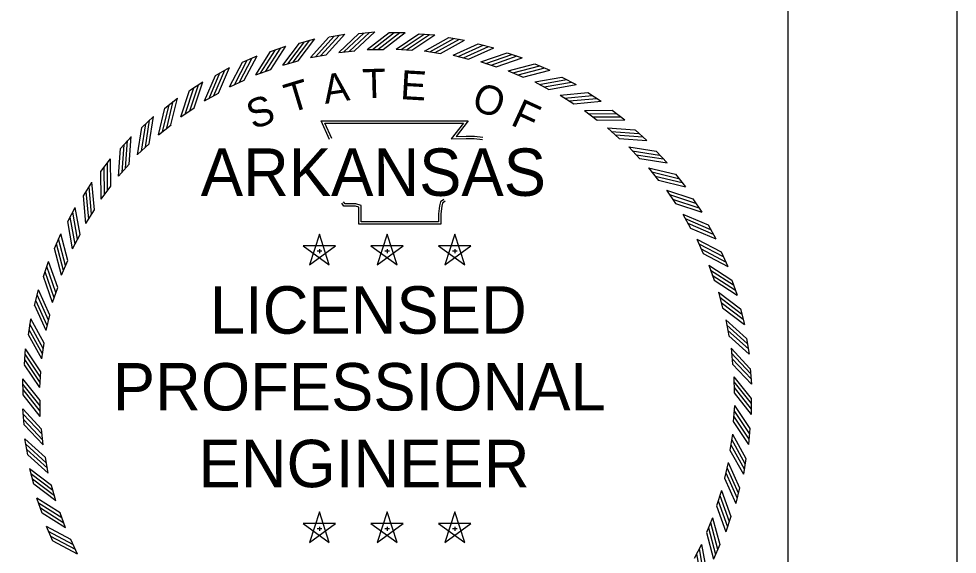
# Model space of a CAD drawing. Extents: x 0 to 1228740, y 0 to 152440.
# Drawn here: x 30.801 to 34, y 18.239 to 20.064 of the extents above; entities that cross this region are included whole.
import ezdxf

# ---------------------------------------------------------------- set-up
doc = ezdxf.new("R2010")
doc.units = 0
doc.layers.add('R_Border', color=7, linetype='Continuous')
doc.layers.add('STAMP', color=7, linetype='Continuous')

msp = doc.modelspace()

# ---------------------------------------------------------------- linework, layer by layer
at = {"layer": 'R_Border'}
msp.add_line((33.4231, 0.5768), (33.4231, 21.4232), dxfattribs=at)
msp.add_lwpolyline([(33.9999, 22), (0, 22), (0, 0), (33.9999, 0)], close=True, dxfattribs=at)
at = {"layer": 'STAMP'}
for p, q in [((31.7579, 19.981), (31.8105, 19.9948)), ((31.8584, 20.0015), (31.912, 20.0109)), ((31.9602, 20.0137), (32.0144, 20.0186)), ((32.0633, 20.0167), (32.1177, 20.0167)), ((32.1652, 20.0126), (32.2194, 20.0086)), ((32.2669, 19.9994), (32.3206, 19.9909)), ((31.6595, 19.9522), (31.7108, 19.9703)), ((32.3671, 19.9778), (32.42, 19.965)), ((31.5637, 19.9154), (31.6134, 19.9377)), ((31.7953, 19.9316), (31.849, 19.941)), ((31.8916, 19.9492), (31.9459, 19.9542)), ((31.989, 19.9588), (32.0435, 19.9588)), ((32.0869, 19.9603), (32.1413, 19.9563)), ((32.1845, 19.9538), (32.2384, 19.9453)), ((32.2813, 19.9392), (32.3343, 19.9263)), ((32.4653, 19.9481), (32.5169, 19.9309)), ((31.7008, 19.9061), (31.7536, 19.9199)), ((32.3766, 19.9166), (32.4283, 19.8994)), ((32.5606, 19.9103), (32.6107, 19.8889)), ((31.4714, 19.8708), (31.519, 19.8972)), ((31.6088, 19.8729), (31.6602, 19.891)), ((32.4696, 19.8863), (32.5198, 19.8648)), ((31.383, 19.8188), (31.4283, 19.849)), ((31.5198, 19.8321), (31.5695, 19.8545)), ((32.5598, 19.8484), (32.608, 19.8229)), ((32.6526, 19.8648), (32.7006, 19.8393)), ((31.4344, 19.7842), (31.4821, 19.8106)), ((32.6466, 19.8031), (32.6926, 19.7737)), ((32.7404, 19.8119), (32.7862, 19.7825)), ((31.2992, 19.7596), (31.3419, 19.7934)), ((31.3533, 19.7294), (31.3987, 19.7597)), ((32.7294, 19.7509), (32.7727, 19.7178)), ((32.8236, 19.7518), (32.8668, 19.7188)), ((31.2206, 19.6937), (31.2603, 19.7309)), ((31.277, 19.6681), (31.3198, 19.702)), ((32.8076, 19.692), (32.848, 19.6554)), ((32.9015, 19.6851), (32.9418, 19.6487)), ((31.1477, 19.6216), (31.1842, 19.6619)), ((31.2061, 19.6007), (31.2459, 19.638)), ((32.8806, 19.6268), (32.9179, 19.587)), ((32.9736, 19.6123), (33.0108, 19.5726)), ((31.0811, 19.5437), (31.1141, 19.5869)), ((31.1409, 19.5277), (31.1775, 19.5681)), ((32.948, 19.5559), (32.9819, 19.5131)), ((33.0395, 19.5337), (33.0733, 19.491)), ((31.021, 19.4605), (31.0504, 19.5063)), ((31.082, 19.4495), (31.1151, 19.4928)), ((33.0093, 19.4796), (33.0396, 19.4342)), ((30.9681, 19.3727), (30.9935, 19.4207)), ((33.0987, 19.4499), (33.1289, 19.4046)), ((31.0298, 19.3667), (31.0592, 19.4127)), ((33.0641, 19.3985), (33.0905, 19.3507)), ((33.1507, 19.3615), (33.1771, 19.3139)), ((30.9226, 19.2807), (30.944, 19.3308)), ((30.9845, 19.28), (31.01, 19.3281)), ((31.8255, 19.3302), (31.7915, 19.2258)), ((31.8594, 19.2258), (31.8256, 19.3303)), ((32.0563, 19.3302), (32.0223, 19.2258)), ((32.0902, 19.2258), (32.0564, 19.3303)), ((32.2871, 19.3302), (32.253, 19.2258)), ((32.321, 19.2258), (32.2871, 19.3303)), ((31.8804, 19.2904), (31.7705, 19.2905)), ((32.1112, 19.2904), (32.0013, 19.2905)), ((32.3419, 19.2904), (32.2321, 19.2905)), ((33.112, 19.3131), (33.1344, 19.2634)), ((31.7706, 19.2904), (31.8594, 19.2257)), ((31.7916, 19.2258), (31.8805, 19.2903)), ((31.8177, 19.2728), (31.834, 19.2728)), ((31.8256, 19.2787), (31.8256, 19.2649)), ((32.0014, 19.2904), (32.0902, 19.2257)), ((32.0224, 19.2258), (32.1113, 19.2903)), ((32.0485, 19.2728), (32.0648, 19.2728)), ((32.0564, 19.2787), (32.0564, 19.2649)), ((32.2322, 19.2904), (32.321, 19.2257)), ((32.2532, 19.2258), (32.3421, 19.2903)), ((32.2793, 19.2728), (32.2956, 19.2728)), ((32.2872, 19.2787), (32.2872, 19.2649)), ((33.1953, 19.2692), (33.2176, 19.2195)), ((30.8848, 19.1854), (30.902, 19.237)), ((30.9466, 19.1897), (30.9681, 19.2399)), ((33.1528, 19.2241), (33.1709, 19.1727)), ((33.2321, 19.1734), (33.2502, 19.1221)), ((30.855, 19.0873), (30.8679, 19.1401)), ((30.9163, 19.0967), (30.9335, 19.1484)), ((33.186, 19.1321), (33.1998, 19.0793)), ((33.2609, 19.075), (33.2747, 19.0224)), ((30.8335, 18.987), (30.8419, 19.0407)), ((30.8937, 19.0014), (30.9066, 19.0544)), ((33.2115, 19.0376), (33.2209, 18.9839)), ((33.2814, 18.9745), (33.2908, 18.9209)), ((30.8203, 18.8853), (30.8243, 18.9395)), ((30.8791, 18.9046), (30.8876, 18.9585)), ((33.2291, 18.9413), (33.2341, 18.887)), ((30.8726, 18.807), (30.8766, 18.8614)), ((33.2387, 18.8439), (33.2392, 18.7893)), ((33.2936, 18.8727), (33.2985, 18.8185)), ((30.8155, 18.7828), (30.815, 18.8372)), ((30.8741, 18.7091), (30.8736, 18.7637)), ((33.2973, 18.7702), (33.2978, 18.7158)), ((30.8192, 18.6803), (30.8142, 18.7345)), ((33.2402, 18.746), (33.2362, 18.6916)), ((30.8837, 18.6117), (30.8787, 18.666)), ((33.2925, 18.6677), (33.2885, 18.6135)), ((30.8314, 18.5785), (30.822, 18.6321)), ((33.2337, 18.6484), (33.2252, 18.5945)), ((30.9013, 18.5154), (30.8918, 18.5691)), ((33.2793, 18.566), (33.2708, 18.5123)), ((30.8519, 18.478), (30.8381, 18.5306)), ((33.2191, 18.5516), (33.2062, 18.4986)), ((30.9268, 18.4209), (30.9129, 18.4737)), ((33.2577, 18.4657), (33.2449, 18.4129)), ((30.8807, 18.3796), (30.8626, 18.4309)), ((33.1965, 18.4563), (33.1793, 18.4046)), ((30.96, 18.3289), (30.9419, 18.3803)), ((31.8255, 18.384), (31.7915, 18.2795)), ((31.8594, 18.2796), (31.8256, 18.3841)), ((32.0563, 18.384), (32.0223, 18.2795)), ((32.0902, 18.2796), (32.0564, 18.3841)), ((32.2871, 18.384), (32.253, 18.2795)), ((32.321, 18.2796), (32.2871, 18.3841)), ((33.1662, 18.3633), (33.1447, 18.3131)), ((33.228, 18.3676), (33.2108, 18.316)), ((30.9175, 18.2838), (30.8952, 18.3335)), ((31.8804, 18.3441), (31.7705, 18.3442)), ((31.7706, 18.3441), (31.8594, 18.2795)), ((31.7916, 18.2796), (31.8805, 18.3441)), ((31.8256, 18.3324), (31.8256, 18.3186)), ((32.1112, 18.3441), (32.0013, 18.3442)), ((32.0014, 18.3441), (32.0902, 18.2795)), ((32.0224, 18.2796), (32.1113, 18.3441)), ((32.0564, 18.3324), (32.0564, 18.3186)), ((32.3419, 18.3441), (32.2321, 18.3442)), ((32.2322, 18.3441), (32.321, 18.2795)), ((32.2532, 18.2796), (32.3421, 18.3441)), ((32.2872, 18.3324), (32.2872, 18.3186)), ((31.8177, 18.3266), (31.834, 18.3266)), ((32.0485, 18.3266), (32.0648, 18.3266)), ((32.2793, 18.3266), (32.2956, 18.3266)), ((31.0007, 18.2399), (30.9784, 18.2896)), ((33.1283, 18.273), (33.1027, 18.2248)), ((33.1902, 18.2722), (33.1688, 18.2222))]:
    msp.add_line(p, q, dxfattribs=at)
for points in [[(31.7535, 19.92), (31.8106, 19.9948)], [(31.7953, 19.9315), (31.8583, 20.0014)], [(31.8126, 19.9344), (31.8756, 20.0043)], [(31.8311, 19.9381), (31.8941, 20.008)], [(31.849, 19.9411), (31.912, 20.011)], [(31.8916, 19.9491), (31.9602, 20.0136)], [(31.909, 19.9506), (31.9776, 20.015)], [(31.9278, 19.9527), (31.9964, 20.0172)], [(31.9458, 19.9542), (32.0145, 20.0187)], [(31.989, 19.9587), (32.0632, 20.0166)], [(32.0065, 19.9586), (32.0807, 20.0165)], [(32.0254, 19.959), (32.0996, 20.0169)], [(32.0435, 19.9588), (32.1177, 20.0167)], [(32.0868, 19.9603), (32.1651, 20.0126)], [(32.1043, 19.9588), (32.1825, 20.0111)], [(32.1231, 19.9579), (32.2014, 20.0101)], [(32.1412, 19.9564), (32.2195, 20.0087)], [(32.1845, 19.9537), (32.2668, 19.9994)], [(32.2017, 19.9508), (32.2841, 19.9965)], [(31.643, 19.8852), (31.6937, 19.9645)], [(31.6601, 19.8911), (31.7108, 19.9704)], [(31.7008, 19.906), (31.7579, 19.9809)], [(31.7178, 19.9103), (31.7748, 19.9852)], [(31.7359, 19.9155), (31.793, 19.9904)], [(32.2205, 19.9483), (32.3028, 19.994)], [(32.2383, 19.9453), (32.3207, 19.991)], [(32.2812, 19.9391), (32.3671, 19.9778)], [(32.2982, 19.9348), (32.384, 19.9735)], [(32.3167, 19.9308), (32.4025, 19.9695)], [(32.3342, 19.9263), (32.4201, 19.965)], [(31.5528, 19.8472), (31.5968, 19.9305)], [(31.5694, 19.8545), (31.6134, 19.9378)], [(31.6087, 19.8728), (31.6594, 19.9521)], [(31.6253, 19.8785), (31.676, 19.9578)], [(32.3765, 19.9166), (32.4652, 19.9481)], [(32.393, 19.9109), (32.4818, 19.9424)], [(32.4111, 19.9053), (32.4998, 19.9368)], [(32.4282, 19.8994), (32.517, 19.9309)], [(31.5197, 19.8321), (31.5637, 19.9153)], [(31.5358, 19.8391), (31.5797, 19.9224)], [(32.4695, 19.8863), (32.5606, 19.9103)], [(32.4856, 19.8792), (32.5766, 19.9033)], [(31.4344, 19.7842), (31.4713, 19.8707)], [(31.4498, 19.7925), (31.4867, 19.8791)], [(31.4661, 19.802), (31.5031, 19.8886)], [(31.4821, 19.8106), (31.519, 19.8972)], [(32.5031, 19.8722), (32.5941, 19.8962)], [(32.5197, 19.8649), (32.6107, 19.8889)], [(31.3835, 19.7498), (31.4131, 19.8391)], [(31.3986, 19.7597), (31.4283, 19.849)], [(32.5598, 19.8484), (32.6525, 19.8648)], [(32.5752, 19.84), (32.6679, 19.8565)], [(32.5921, 19.8315), (32.6848, 19.848)], [(32.608, 19.8229), (32.7007, 19.8394)], [(31.3533, 19.7293), (31.383, 19.8187)], [(31.368, 19.7389), (31.3976, 19.8283)], [(32.6466, 19.8031), (32.7403, 19.8119)], [(32.6612, 19.7935), (32.755, 19.8023)], [(31.2908, 19.6788), (31.313, 19.7703)], [(31.3054, 19.6909), (31.3276, 19.7824)], [(31.3197, 19.702), (31.3419, 19.7935)], [(32.6774, 19.7837), (32.7711, 19.7924)], [(32.6925, 19.7738), (32.7863, 19.7825)], [(31.277, 19.668), (31.2992, 19.7595)], [(32.7293, 19.7509), (32.8235, 19.7518)], [(32.7431, 19.7401), (32.8373, 19.7411)], [(31.2324, 19.6257), (31.247, 19.7187)], [(31.2458, 19.638), (31.2603, 19.731)], [(31.8606, 19.6525), (31.8316, 19.7154), (32.3333, 19.7156), (32.2914, 19.663), (32.3255, 19.6634), (32.354, 19.6638), (32.3824, 19.6607)], [(31.8678, 19.6559), (31.844, 19.7074), (32.3169, 19.7077), (32.2748, 19.6548), (32.3256, 19.6555), (32.3536, 19.6558), (32.3816, 19.6528)], [(32.7584, 19.729), (32.8526, 19.7299)], [(32.7727, 19.7179), (32.8669, 19.7188)], [(31.2061, 19.6006), (31.2206, 19.6936)], [(31.2189, 19.6125), (31.2335, 19.7055)], [(32.8075, 19.692), (32.9014, 19.6852)], [(32.8204, 19.6801), (32.9143, 19.6733)], [(31.1651, 19.5548), (31.172, 19.6487)], [(31.1774, 19.5681), (31.1842, 19.662)], [(32.8347, 19.6678), (32.9286, 19.6609)], [(32.848, 19.6555), (32.9419, 19.6487)], [(31.1409, 19.5276), (31.1477, 19.6215)], [(31.1528, 19.5405), (31.1596, 19.6344)], [(32.8805, 19.6268), (32.9735, 19.6123)], [(32.8924, 19.6139), (32.9854, 19.5994)], [(31.115, 19.4928), (31.1141, 19.587)], [(32.9056, 19.6004), (32.9986, 19.5859)], [(32.9179, 19.5871), (33.0109, 19.5726)], [(31.0928, 19.4632), (31.0918, 19.5574)], [(31.1039, 19.4785), (31.1029, 19.5727)], [(32.9479, 19.5559), (33.0394, 19.5337)], [(31.082, 19.4494), (31.0811, 19.5436)], [(32.9587, 19.5421), (33.0502, 19.5199)], [(32.9708, 19.5275), (33.0622, 19.5053)], [(31.0492, 19.3975), (31.0405, 19.4912)], [(31.0591, 19.4126), (31.0504, 19.5064)], [(32.9819, 19.5132), (33.0734, 19.491)], [(31.0298, 19.3667), (31.021, 19.4604)], [(31.0393, 19.3813), (31.0306, 19.4751)], [(33.0092, 19.4796), (33.0986, 19.4499)], [(33.0188, 19.4649), (33.1082, 19.4353)], [(31.01, 19.3281), (30.9935, 19.4208)], [(32.2543, 19.4423), (32.2457, 19.4353), (32.2429, 19.4249), (32.24, 19.3989), (32.24, 19.3642), (31.9599, 19.3642), (31.9599, 19.411), (31.9599, 19.4214), (31.9486, 19.4249), (31.9087, 19.4249), (31.9016, 19.4357)], [(32.2493, 19.4484), (32.2387, 19.4399), (32.235, 19.4264), (32.2321, 19.3993), (32.2321, 19.3721), (31.9679, 19.3721), (31.9679, 19.411), (31.9679, 19.4273), (31.9497, 19.4328), (31.913, 19.4328), (31.9083, 19.4401)], [(33.0297, 19.4494), (33.119, 19.4198)], [(33.0396, 19.4343), (33.1289, 19.4046)], [(30.9929, 19.2953), (30.9764, 19.388)], [(31.0013, 19.3122), (30.9849, 19.4049)], [(33.064, 19.3985), (33.1506, 19.3616)], [(30.9845, 19.2799), (30.9681, 19.3726)], [(33.0724, 19.3831), (33.159, 19.3462)], [(33.0819, 19.3668), (33.1685, 19.3298)], [(30.968, 19.2398), (30.944, 19.3308)], [(33.0905, 19.3508), (33.1771, 19.3139)], [(30.9537, 19.2057), (30.9296, 19.2967)], [(30.9607, 19.2232), (30.9367, 19.3142)], [(33.112, 19.3132), (33.1952, 19.2692)], [(33.119, 19.2971), (33.2023, 19.2532)], [(30.9466, 19.1896), (30.9226, 19.2807)], [(33.1271, 19.2801), (33.2104, 19.2361)], [(33.1344, 19.2635), (33.2177, 19.2195)], [(30.9335, 19.1484), (30.902, 19.2371)], [(30.922, 19.1131), (30.8905, 19.2019)], [(30.9276, 19.1312), (30.8961, 19.2199)], [(33.1527, 19.2242), (33.232, 19.1735)], [(33.1584, 19.2076), (33.2377, 19.1569)], [(30.9163, 19.0966), (30.8848, 19.1853)], [(33.1651, 19.1899), (33.2444, 19.1392)], [(33.1709, 19.1728), (33.2503, 19.1221)], [(30.9066, 19.0544), (30.8679, 19.1402)], [(33.1859, 19.1321), (33.2608, 19.075)], [(30.8981, 19.0183), (30.8594, 19.1041)], [(30.9021, 19.0368), (30.8634, 19.1226)], [(33.1902, 19.1151), (33.2651, 19.0581)], [(30.8938, 19.0013), (30.8551, 19.0872)], [(33.1954, 19.097), (33.2703, 19.0399)], [(33.1999, 19.0794), (33.2747, 19.0223)], [(30.8876, 18.9585), (30.8419, 19.0408)], [(33.2114, 19.0376), (33.2813, 18.9746)], [(30.8821, 18.9218), (30.8364, 19.0042)], [(30.8846, 18.9406), (30.8389, 19.0229)], [(33.2143, 19.0203), (33.2842, 18.9573)], [(30.8792, 18.9046), (30.8335, 18.9869)], [(33.218, 19.0018), (33.2879, 18.9387)], [(33.221, 18.9839), (33.2909, 18.9209)], [(30.8765, 18.8613), (30.8242, 18.9396)], [(33.229, 18.9413), (33.2935, 18.8727)], [(30.875, 18.8432), (30.8227, 18.9215)], [(33.2305, 18.9239), (33.2949, 18.8553)], [(30.8726, 18.8069), (30.8203, 18.8852)], [(30.8741, 18.8244), (30.8218, 18.9026)], [(33.2326, 18.9051), (33.2971, 18.8365)], [(33.2341, 18.887), (33.2986, 18.8184)], [(33.2386, 18.8439), (33.2972, 18.7702)], [(30.8736, 18.7636), (30.815, 18.8373)], [(30.8736, 18.7455), (30.815, 18.8192)], [(33.2386, 18.8264), (33.2972, 18.7527)], [(30.8742, 18.7266), (30.8156, 18.8003)], [(30.8742, 18.7091), (30.8156, 18.7828)], [(33.2392, 18.8075), (33.2978, 18.7338)], [(33.2392, 18.7894), (33.2978, 18.7157)], [(30.8787, 18.666), (30.8142, 18.7346)], [(30.8802, 18.6479), (30.8157, 18.7165)], [(33.2387, 18.7286), (33.291, 18.6503)], [(33.2402, 18.7461), (33.2925, 18.6678)], [(30.8823, 18.6291), (30.8178, 18.6977)], [(33.2363, 18.6917), (33.2885, 18.6134)], [(33.2378, 18.7098), (33.29, 18.6315)], [(30.8838, 18.6117), (30.8193, 18.6803)], [(30.8918, 18.5691), (30.8219, 18.6321)], [(33.2307, 18.6312), (33.2764, 18.5488)], [(33.2336, 18.6484), (33.2793, 18.5661)], [(30.8948, 18.5512), (30.8249, 18.6142)], [(30.8985, 18.5327), (30.8286, 18.5957)], [(33.2252, 18.5945), (33.2709, 18.5122)], [(33.2282, 18.6124), (33.2739, 18.5301)], [(30.9014, 18.5154), (30.8315, 18.5784)], [(30.9129, 18.4736), (30.838, 18.5307)], [(33.2147, 18.5347), (33.2534, 18.4489)], [(33.219, 18.5517), (33.2577, 18.4658)], [(30.9174, 18.456), (30.8425, 18.5131)], [(30.9226, 18.4379), (30.8477, 18.4949)], [(33.2062, 18.4986), (33.2449, 18.4128)], [(33.2107, 18.5162), (33.2493, 18.4304)], [(30.9269, 18.4209), (30.852, 18.478)], [(30.9418, 18.3802), (30.8625, 18.4309)], [(33.1908, 18.4398), (33.2223, 18.3511)], [(33.1965, 18.4564), (33.228, 18.3677)], [(30.9477, 18.3631), (30.8684, 18.4138)], [(30.9544, 18.3454), (30.8751, 18.3961)], [(33.1793, 18.4046), (33.2108, 18.3159)], [(33.1852, 18.4218), (33.2167, 18.3331)], [(30.9601, 18.3288), (30.8808, 18.3795)], [(33.1662, 18.3634), (33.1902, 18.2723)], [(30.9784, 18.2895), (30.8951, 18.3335)], [(33.1591, 18.3473), (33.1832, 18.2563)], [(30.9857, 18.2729), (30.9024, 18.3169)], [(30.9938, 18.2559), (30.9105, 18.2998)], [(33.1448, 18.3132), (33.1688, 18.2222)], [(33.1521, 18.3298), (33.1761, 18.2388)], [(31.0008, 18.2398), (30.9176, 18.2838)], [(33.1282, 18.2731), (33.1447, 18.1804)], [(33.1114, 18.2408), (33.1279, 18.1481)], [(33.1199, 18.2577), (33.1364, 18.165)]]:
    msp.add_lwpolyline(points, dxfattribs=at)

# ---------------------------------------------------------------- texts
for s, rotation, p in [('A', 8.6788, (31.8453, 19.7733)), ('T', 1.4789, (31.9731, 19.793)), ('E', 356.672, (32.0998, 19.79)), ('T', 16.9015, (31.7251, 19.742)), ('O', 341.2218, (32.3401, 19.7561)), ('S', 19.7726, (31.5992, 19.6855)), ('F', 335.3628, (32.4735, 19.7039))]:
    msp.add_text(s, height=0.099, rotation=rotation, dxfattribs=at).set_placement(p)
for s, height, p in [('ARKANSAS', 0.16155, (31.4214, 19.4603)), ('LICENSED', 0.16155, (31.4521, 18.9908)), ('PROFESSIONAL', 0.161547, (31.1214, 18.7292)), ('ENGINEER', 0.16155, (31.4137, 18.4677))]:
    msp.add_text(s, height=height, dxfattribs=at).set_placement(p)

doc.saveas('drawing.dxf')
